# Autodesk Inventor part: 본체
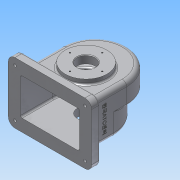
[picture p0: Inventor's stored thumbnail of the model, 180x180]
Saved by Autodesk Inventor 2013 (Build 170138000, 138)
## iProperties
Created: 2017-11
Part Number: 본체
Material: 알루미늄 6061
Document SubType Name: Modeling
Designer: Administrator
Density: 2.71 g/cm^3
Mass: 1079.71 g
Surface Area: 1182.06 cm^2
Volume: 398.417 cm^3
Author: Administrator
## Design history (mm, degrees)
sketch "스케치4"
  geometry: L1 (-75, -65)-(75, -65); L2 (75, -65)-(75, -80); L3 (75, -80)-(-75, -80); L4 (-75, -80)-(-75, -65); 2 further points
  constraints: 8 end point, 2 parallel, 1 horizontal, 1 midpoint, 1 perpendicular, 1 vertical alignment
  dimensions: "d2" = 80 distance from line of L3 point (0, 0); "d3" = 150 distance of L2.end L3.end; "d4" = 15 distance of L1.end L2.end
extrude "돌출1" new body sketch "스케치4" stored distance "d5" = 110; taper "d6" = 0 deg
fillet "모깎기1" dims "d10" = 12
sketch "스케치6"
  geometry: L1 (-58, 0)-(-58, -65); L2 (58, 0)-(58, -65); L3 (-63, -65)-(63, -65) reference; A1 r 58 centre (0, 0) between (-58, 0) and (58, 0); 1 further point
  constraints: 4 end point, 2 point on circle, 2 point on line, 2 tangent, 1 centre point, 1 coincident, 1 parallel, 1 vertical
  dimensions: "d11" = 116 diameter of A1
extrude "돌출2" join sketch "스케치6" distance "d12" = 38; taper "d13" = 0 deg
sketch "스케치7"
  geometry: L1 (58, 0)-(58, -65) reference; L2 (-58, -65)-(-58, 0) reference; L3 (58, -65)-(-58, -65) reference; L4 (-63, -80)-(63, -80) reference; A1 r 58 centre (0, 0) between (58, 0) and (-58, 0) reference; A2 r 58 centre (0, -23) between (58, -23) and (-58, -23)
  constraints: 2 point on circle, 2 point on line, 1 centre point, 1 vertical alignment
  dimensions: "d14" = 116 diameter of A2; "d15" = 57 distance from line of L4 A2.centre
extrude "돌출3" join sketch "스케치7" distance "d16" = 38; taper "d17" = 0 deg
feature "쉘1" dims "d27" = 5
sketch "스케치10"
  geometry: L1 (116, 17)-(116, 83) reference; L2 (10, 17)-(116, 17) reference; L3 (10, 83)-(10, 17) reference; L4 (116, 83)-(10, 83) reference; L5 (0, 0)-(126, 0) reference; L6 (133, 93)-(133, 7) reference; L7 (126, 100)-(0, 100) reference; L8 (-7, 7)-(-7, 93) reference; A1 r 7 centre (0, 7) between (-7, 7) and (0, 0) reference; A2 r 7 centre (126, 7) between (126, 0) and (133, 7) reference; A3 r 7 centre (126, 93) between (133, 93) and (126, 100) reference; A4 r 7 centre (0, 93) between (0, 100) and (-7, 93) reference; 1 further point
extrude "돌출4" join sketch "스케치10" stored distance "d28" = 28; taper "d29" = 0 deg
sketch "스케치11"
  geometry: L1 (-63, -80)-(63, -80) reference; C1 r 31 at (0, -15); A1 r 58 centre (0, -23) between (58, -23) and (-58, -23) reference; 1 further point
  constraints: 1 centre point, 1 vertical alignment
  dimensions: "d33" = 62 diameter of C1; "d34" = 65 distance from line of L1 C1.centre
sketch "스케치12"
  geometry: L1 (-63, -80)-(63, -80) reference; C1 r 37.5 at (0, -15); A1 r 58 centre (0, 0) between (58, 0) and (-58, 0) reference
  constraints: 1 centre point, 1 vertical alignment
  dimensions: "d31" = 75 diameter of C1; "d32" = 65 distance from line of L1 C1.centre
extrude "돌출5" join sketch "스케치11" distance "d35" = 10; taper "d36" = 0 deg
extrude "돌출6" join sketch "스케치12" distance "d37" = 9; taper "d38" = 0 deg
sketch "스케치13"
  geometry: C1 r 31 at (0, 0) reference; C2 r 16 at (0, 0); 1 further point
  constraints: 1 centre point, 1 coincident
  dimensions: "d39" = 32 diameter of C2
extrude "돌출7" cut sketch "스케치13" stored distance "d40" = 9; taper "d41" = 0 deg
node "작업 평면1"
sketch "스케치14"
  geometry: L1 (-12, 12)-(-12, 98) reference; L2 (121, 93)-(5, 93) reference; C1 r 6 at (63, 74); 1 further point
  constraints: 1 centre point
  dimensions: "d45" = 12 diameter of C1; "d46" = 75 distance from line of L1 C1.centre; "d47" = 19 distance from line of L2 C1.centre
extrude "돌출8" join sketch "스케치14" stored distance "d48" = 9; taper "d49" = 0 deg
hole "구멍1" diameter "d52" = 4.459; stored, may be unused: countersink angle "d56" = 90 deg, drill point angle "d58" = 118 deg; dims "d50" = 10, "d51" = 10, "d53" = 6, "d54" = 4, "d55" = 2, "d57" = 8
sketch "스케치15"
  geometry: A1 r 12 centre (0, 98) between (0, 110) and (-12, 98) reference; A2 r 12 centre (0, 12) between (-12, 12) and (0, 0) reference; A3 r 12 centre (126, 12) between (126, 0) and (138, 12) reference; A4 r 12 centre (126, 98) between (138, 98) and (126, 110) reference; 5 further points
  constraints: 4 coincident
hole "구멍2" sketch "스케치15" at (0, 12), (0, 98), (126, 98), (126, 12) diameter "d62" = 5; stored, may be unused: countersink angle "d66" = 90 deg, drill point angle "d68" = 118 deg; dims "d63" = 6, "d64" = 12, "d65" = 5, "d67" = 8
chamfer "모따기1" distance "d69" = 1; stored, may be unused: second distance "d70" = 2, angle "d71" = 45 deg
fillet "모깎기3" dims "d73" = 8
fillet "모깎기4" dims "d74" = 3
fillet "모깎기5" dims "d75" = 3
sketch "스케치16" dims "d40" = 9, "d41" = 0
  geometry: L1 (-8, 62)-(-8, 0) reference; L2 (-13, -18)-(73, -18) reference; 2 further points
  constraints: 1 other
  dimensions: "d77" = 38 distance from line of L1 point (30, 22); "d78" = 40 distance from line of point (30, 22) L2
feature "엠보싱1" sketch "스케치16" dims "d2" = 80, "d3" = 150, "d4" = 15, "d79" = 0.5, "d80" = 0
fillet "모깎기7" dims "d81" = 3
sketch "스케치17"
  geometry: C1 r 37.5 at (0, 0) reference; 2 further points
  constraints: 1 vertical alignment
  dimensions: "d82" = 29 distance of point (0, 29) C1.centre
hole "구멍3" sketch "스케치17" at (0, 29) diameter "d83" = 2.459; stored, may be unused: countersink angle "d87" = 90 deg, drill point angle "d89" = 118 deg; dims "d84" = 6, "d85" = 12, "d86" = 5, "d88" = 8
sketch "스케치18"
  geometry: C1 r 31 at (0, 0) reference; 2 further points
  constraints: 1 vertical alignment
  dimensions: "d93" = 26 distance of C1.centre point (0, 26)
hole "구멍4" sketch "스케치18" at (0, 26) diameter "d94" = 2.459; stored, may be unused: countersink angle "d98" = 90 deg, drill point angle "d100" = 118 deg; dims "d95" = 6, "d96" = 12, "d97" = 5, "d99" = 8
node "솔리드1"
pattern_circular "원형 패턴1" dims angle "d91" = 360 deg
pattern_circular "원형 패턴2" dims angle "d102" = 360 deg
other parameters: "d42" = -144
